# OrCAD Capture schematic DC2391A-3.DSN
size Custom; title: LOW POWER  I/Q  MODULATOR 0.7GHz - 3.8GHz; rev: 3; company: TM
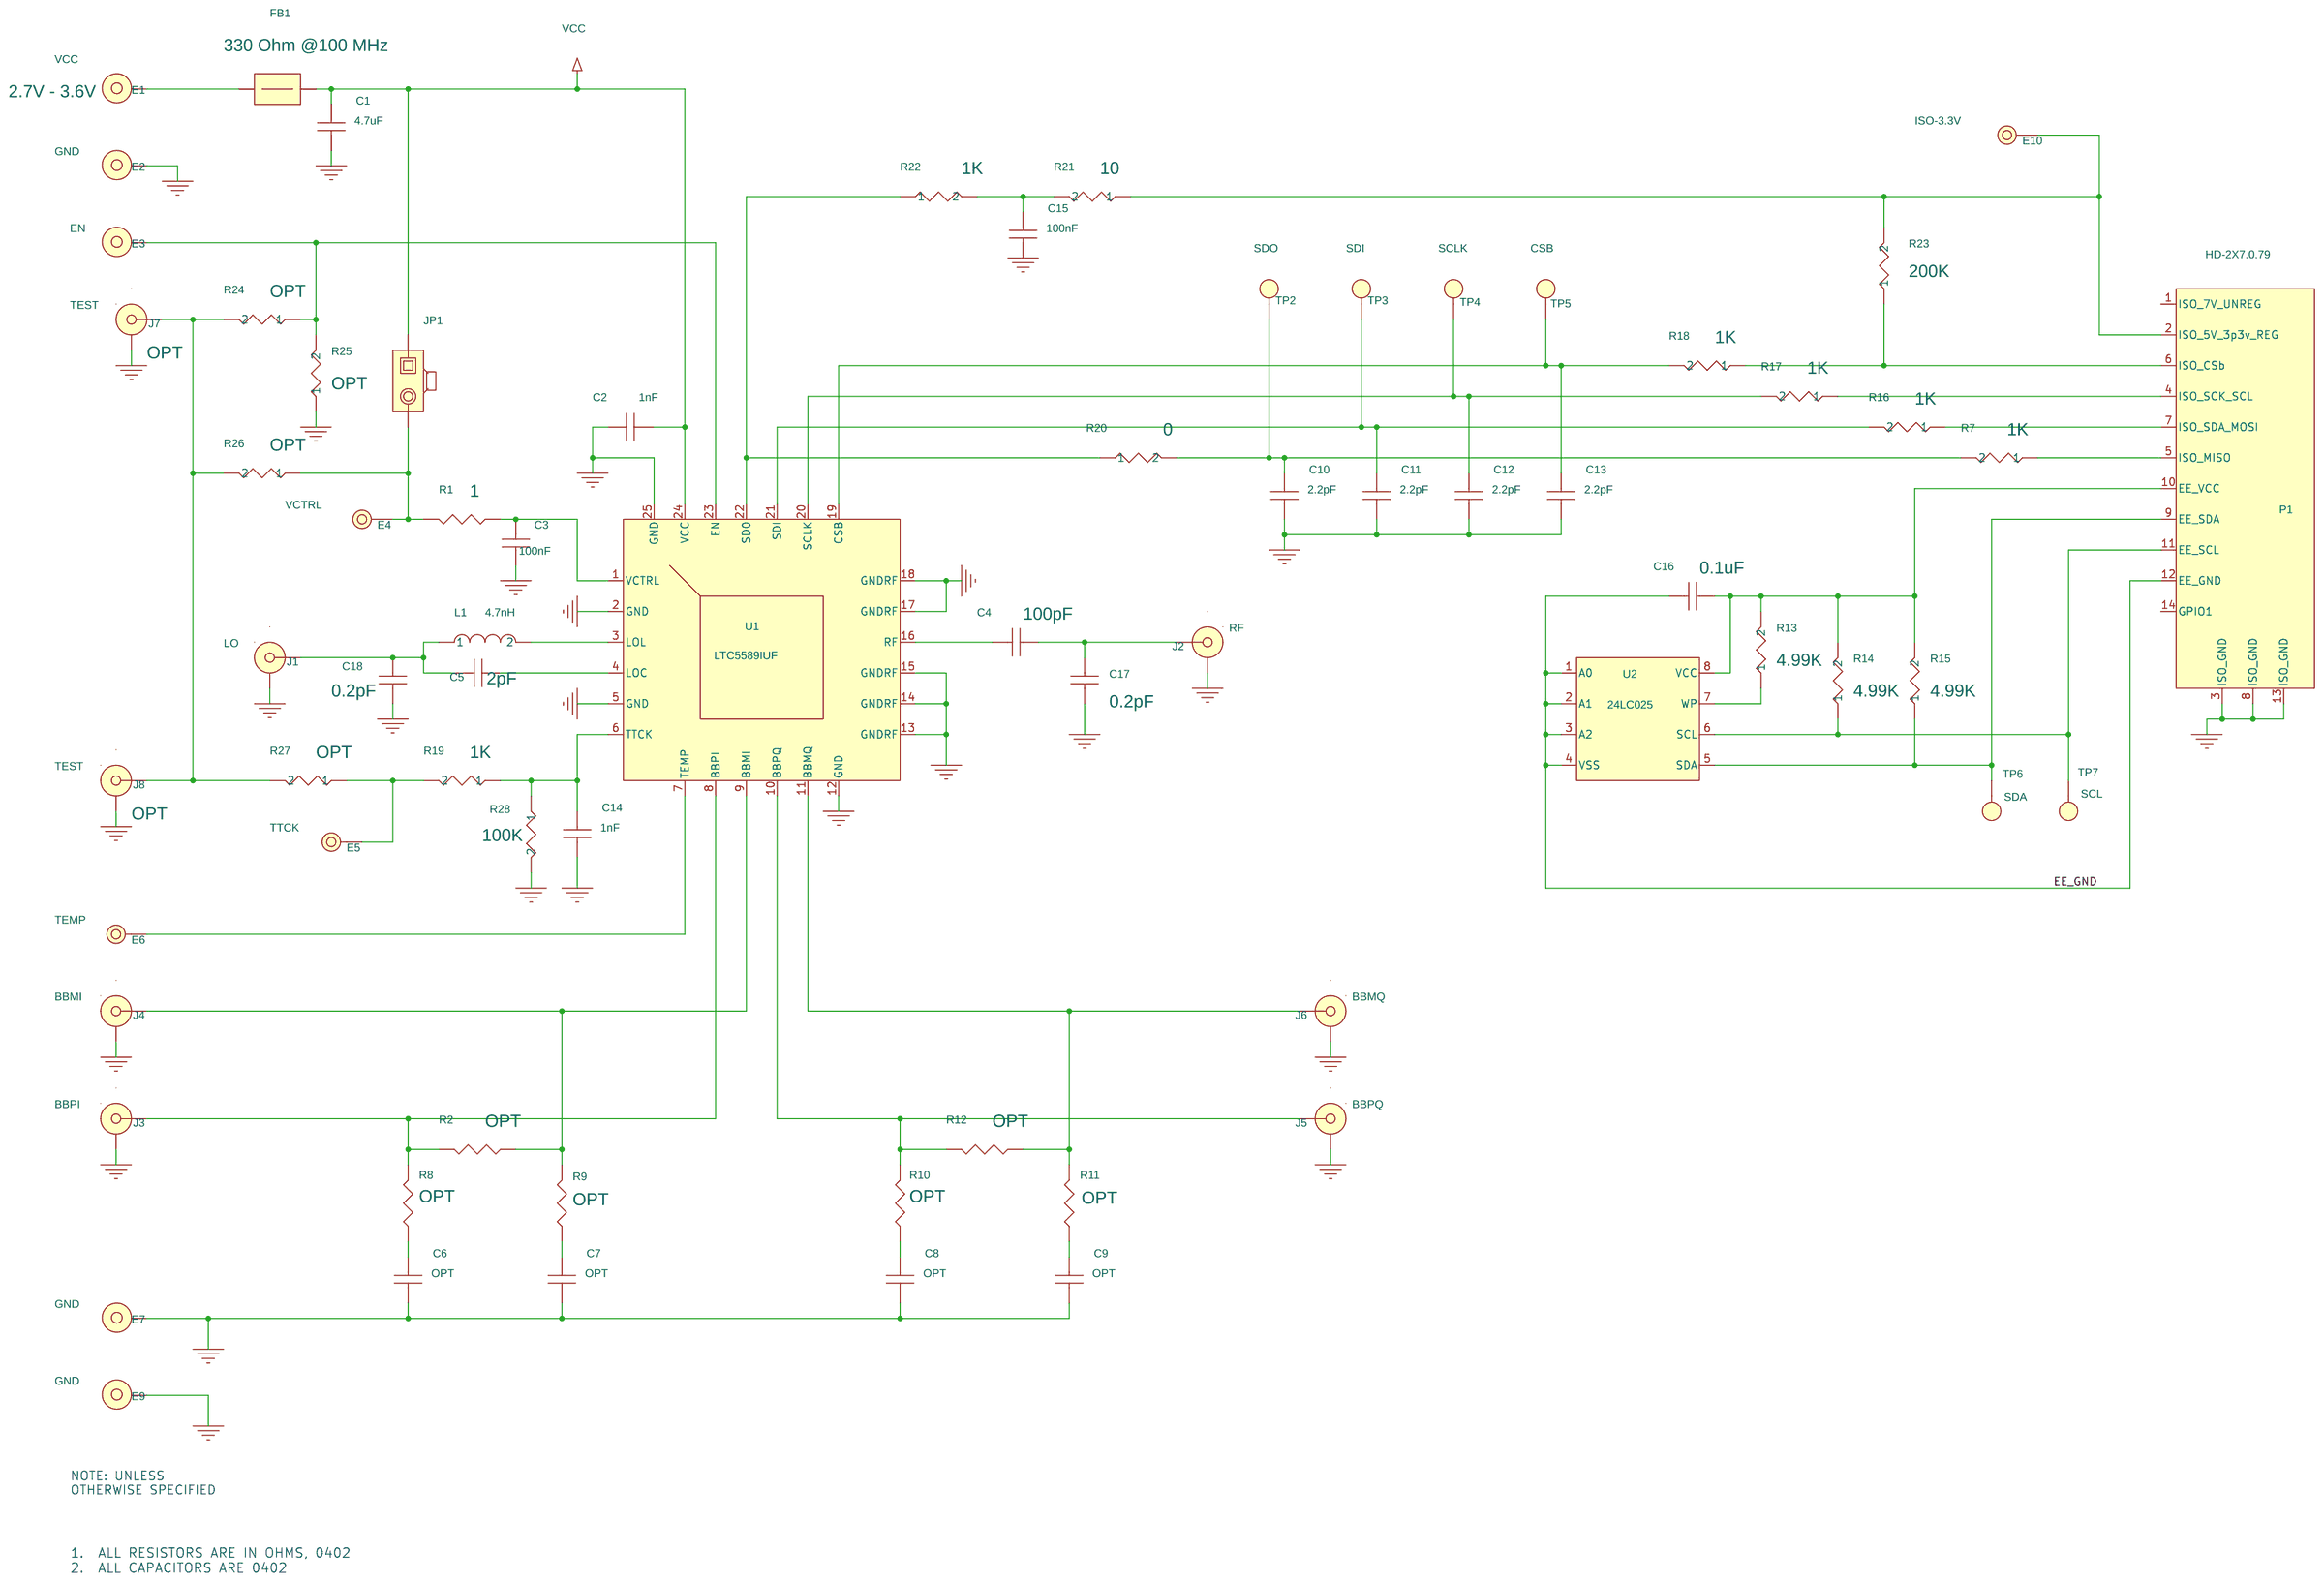
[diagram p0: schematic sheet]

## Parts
C1  4.7uF  [0603]
C2  1nF  [0402]
C3  100nF  [0402]
C4  100pF  [0402]
C5  2pF  [0402]
C6  OPT  [0402]
C7  OPT  [0402]
C8  OPT  [0402]
C9  OPT  [0402]
C10  2.2pF  [0402]
C11  2.2pF  [0402]
C12  2.2pF  [0402]
C13  2.2pF  [0402]
C14  1nF  [0402]
C15  100nF  [0402]
C16  0.1uF  [0402]
C17  0.2pF  [0402]
C18  0.2pF  [0402]
E1  VCC  [MM/2501]
E2  GND  [MM/2501]
E3  EN  [MM/2501]
E4  VCTRL  [MM/2308]
E5  TTCK  [MM/2308]
E6  TEMP  [MM/2308]
E7  GND  [MM/2501]
E9  GND  [MM/2501]
E10  ISO-3.3V  [MM/2308]
FB1  FERRITE BEAD  [0603]
J1  LO  [CON\SMA-END]
J2  RF  [CON\SMA-END]
J3  BBPI  [CON\SMA-END]
J4  BBMI  [CON\SMA-END]
J5  BBPQ  [CON\SMA-END]
J6  BBMQ  [CON\SMA-END]
J7  TEST  [CON\SMA-END]
J8  TEST  [CON\SMA-END]
JP1  3 Pins 2mm Ctrs.  [HD-1X2-079]
L1  4.7nH  [0402]
P1  HD-2X7.0.79  [HD2X7-079-MOLEX]
R1  1  [0402]
R2  OPT  [0402]
R7  1K  [0402]
R8  OPT  [0402]
R9  OPT  [0402]
R10  OPT  [0402]
R11  OPT  [0402]
R12  OPT  [0402]
R13  4.99K  [0402]
R14  4.99K  [0402]
R15  4.99K  [0402]
R16  1K  [0402]
R17  1K  [0402]
R18  1K  [0402]
R19  1K  [0402]
R20  0  [0402]
R21  10  [0402]
R22  1K  [0402]
R23  200K  [0402]
R24  OPT  [0402]
R25  OPT  [0402]
R26  OPT  [0402]
R27  OPT  [0402]
R28  100K  [0402]
TP2  SDO  [TP-SM-30]
TP3  SDI  [TP-SM-30]
TP4  SCLK  [TP-SM-30]
TP5  CSB  [TP-SM-30]
TP6  SDA  [TP-SM-30]
TP7  SCL  [TP-SM-30]
U1  LTC5589IUF  [QFN24-4X4]
U2  24LC025  [ST-4.4MMTSSOP]
XJP5  2mm Ctrs.

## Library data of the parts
C1-C3 C6-C15 = CAP_NP: CAP, 0603, 1uF, 10%, 10V, X5R; Part Number: AVX 0603ZD105KAT
C4 C5 C16-C18 = CAP_NP: 6V: 0603; OPTIONAL: OPTIONAL
E1 = CON_KEY_575-4_2: 4th Part Field: 2.7V - 3.6V
E2 E3 E7 E9 = CON_KEY_575-4_2
E4-E6 E10 = CON_KEY_575-4_1
FB1 = FERRITE_BEAD,_120_OHM,_1206_0: 1: 330 Ohm @100 MHz
J1-J6 = CON_SMA-END_3
J7 J8 = CON_SMA-END_3: 1: OPT
JP1 = TMP_0: HEADER, 3 PIN, .079
L1 = INDUCTOR: 0805: 0603; DO3316P-682: DO3316P-682
P1 = CONN.,_JTAG,_2X5,_0_0.100
R1 R2 R8-R12 R18 = R_1: 0603: 0603; 1%: 1%
R7 = R_4: 0603: 0603; 1%: 1%
R13 = R_5: 0603: 0603; 1%: 1%
R14 = R_8: 0603: 0603; 1%: 1%
R15 = R_14: 0603: 0603; 1%: 1%
R16 = R_3: 0603: 0603; 1%: 1%
R17 = R_12: 0603: 0603; 1%: 1%
R19 = R_13: 0603: 0603; 1%: 1%
R20 = R_10: 0603: 0603; 1%: 1%
R21 = R: 0603: 0603; 1%: 1%
R22 = R_15: 0603: 0603; 1%: 1%
R23 = R_11: 0603: 0603; 1%: 1%
R24 = R_2: 0603: 0603; 1%: 1%
R25 = R_16: 0603: 0603; 1%: 1%
R26 = R_9: 0603: 0603; 1%: 1%
R27 = R_7: 0603: 0603; 1%: 1%
R28 = R_6: 0603: 0603; 1%: 1%
TP2 = CON_KEY_575-4_3
TP3 = CON_KEY_575-4_4
TP4 = CON_KEY_575-4_5
TP5 = CON_KEY_575-4_6
TP6 TP7 = CON_KEY_575-4_0
U1 = LTC5599_4
U2 = 24LC025_0
XJP5 = CommconCCIJ2MM-138G

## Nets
GND: C1.2 C2.1 C3.1 C6.2 C7.2 C8.2 C9.2 C10.2 C11.2 C12.2 C13.2 C14.2 C15.2 C17.2 C18.2 E2.1 E7.1 E9.1 J1.2(GND) J1.3(GND) J1.4(GND) J1.5(GND) J2.2(GND) J2.3(GND) J2.4(GND) J2.5(GND) J3.2(GND) J3.3(GND) J3.4(GND) J3.5(GND) J4.2(GND) J4.3(GND) J4.4(GND) J4.5(GND) J5.2(GND) J5.3(GND) J5.4(GND) J5.5(GND) J6.2(GND) J6.3(GND) J6.4(GND) J6.5(GND) J7.2(GND) J7.3(GND) J7.4(GND) J7.5(GND) J8.2(GND) J8.3(GND) J8.4(GND) J8.5(GND) P1.3(ISO_GND) P1.8(ISO_GND) P1.13(ISO_GND) R25.1 R28.2 U1.2(GND) U1.5(GND) U1.12(GND) U1.13(GNDRF) U1.14(GNDRF) U1.15(GNDRF) U1.17(GNDRF) U1.18(GNDRF) U1.25(GND)
VCC: C1.1 C2.2 FB1.2 JP1.1 U1.24(VCC)
EE_GND: C16.2 P1.12(EE_GND) U2.1(A0) U2.2(A1) U2.3(A2) U2.4(VSS)
N17175110: J5.1(CENTER) R10.2 R12.2 U1.10(BBPQ)
N17175382: J4.1(CENTER) R2.1 R9.2 U1.9(BBMI)
N17175454: E3.1 R24.1 R25.2 U1.23(EN)
N17175524: L1.2 U1.3(LOL)
N17175540: C5.1 U1.4(LOC)
N17175584: C5.2 C18.1 J1.1(CENTER) L1.1
N17175586: C3.2 R1.1 U1.1(VCTRL)
N17175657: J3.1(CENTER) R2.2 R8.2 U1.8(BBPI)
N17175719: E1.1 FB1.1
N17175826: J6.1(CENTER) R11.2 R12.1 U1.11(BBMQ)
N17176107: E4.1 JP1.2 R1.2 R26.1
N17176146: E6.1 U1.7(TEMP)
N17179329: C4.2 U1.16(RF)
N17179622: C4.1 C17.1 J2.1(CENTER)
N17384031: C14.1 R19.1 R28.1 U1.6(TTCK)
N17479576: C10.1 R7.2 R20.2 TP2.1
N17479578: C11.1 R16.2 TP3.1 U1.21(SDI)
N17479592: C13.1 R18.2 TP5.1 U1.19(CSB)
N17479604: P1.5(ISO_MISO) R7.1
N17479610: P1.6(ISO_CSb) R18.1 R23.1
N17479616: P1.7(ISO_SDA_MOSI) R16.1
N17479630: C12.1 R17.2 TP4.1 U1.20(SCLK)
N17479664: P1.4(ISO_SCK_SCL) R17.1
N17479684: R13.1 U2.7(WP)
N17479688: P1.11(EE_SCL) R14.1 TP7.1 U2.6(SCL)
N17479690: P1.9(EE_SDA) R15.1 TP6.1 U2.5(SDA)
N17479840: C16.1 P1.10(EE_VCC) R13.2 R14.2 R15.2 U2.8(VCC)
N17483167: R20.1 R22.1 U1.22(SD0)
N17484033: E10.1 P1.2(ISO_5V_3p3v_REG) R21.1 R23.2
N17485870: C15.1 R21.2 R22.2
N17491303: J7.1(CENTER) J8.1(CENTER) R24.2 R26.2 R27.2
N17496924: E5.1 R19.2 R27.1
N17502009: C6.1 R8.1
N17502010: C7.1 R9.1
N17502011: C8.1 R10.1
N17502012: C9.1 R11.1

Not connected (* = marked no-connect by the designer): P1 1(ISO_7V_UNREG) 14(GPIO1)

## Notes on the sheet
- NOTE: UNLESS
  OTHERWISE SPECIFIED
- 1.  ALL RESISTORS ARE IN OHMS, 0402
  2.  ALL CAPACITORS ARE 0402
